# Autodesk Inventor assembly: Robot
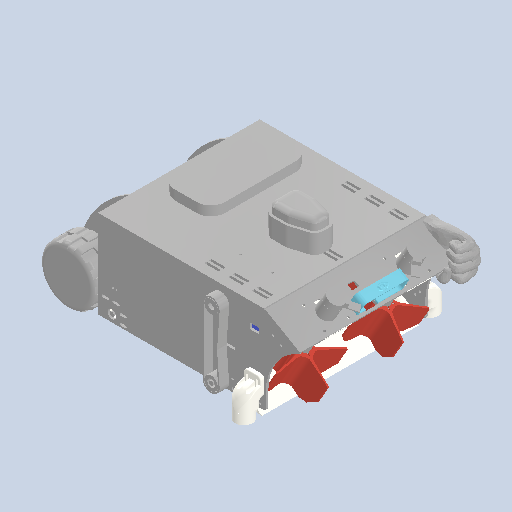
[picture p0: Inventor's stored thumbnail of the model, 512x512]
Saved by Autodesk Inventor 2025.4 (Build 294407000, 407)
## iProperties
Created: 2026-06
Part Number: Robot
Document SubType Name: Assembly
Designer: AdminForWorker
Title: Robot v95
Author: AdminForWorker
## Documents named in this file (14)
- c:\worker\convert-fusion-r03-cosv3\tmp\job-1\197\temp\files\732f0928-61d3-46c1-a194-566e71e2638b\9d352d10-8130-4545-9c63-16a8f3545512.iam
- c:\worker\convert-fusion-r03-cosv3\tmp\job-1\197\temp\files\732f0928-61d3-46c1-a194-566e71e2638b\Moteur + Roue v3.ipt
- c:\worker\convert-fusion-r03-cosv3\tmp\job-1\197\temp\files\732f0928-61d3-46c1-a194-566e71e2638b\Moteur v4.ipt
- c:\worker\convert-fusion-r03-cosv3\tmp\job-1\197\temp\files\732f0928-61d3-46c1-a194-566e71e2638b\Moteur v3(Symétrie miroir).ipt
- c:\worker\convert-fusion-r03-cosv3\tmp\job-1\197\temp\files\732f0928-61d3-46c1-a194-566e71e2638b\Moteur + Roue v1(Symétrie miroir).ipt
- c:\worker\convert-fusion-r03-cosv3\tmp\job-1\197\temp\files\732f0928-61d3-46c1-a194-566e71e2638b\Bille de manutention v16.ipt
- c:\worker\convert-fusion-r03-cosv3\tmp\job-1\197\temp\files\732f0928-61d3-46c1-a194-566e71e2638b\Bille + Main v7.ipt
- c:\worker\convert-fusion-r03-cosv3\tmp\job-1\197\temp\files\732f0928-61d3-46c1-a194-566e71e2638b\Camera v15.ipt
- c:\worker\convert-fusion-r03-cosv3\tmp\job-1\197\temp\files\732f0928-61d3-46c1-a194-566e71e2638b\OLD Frame.ipt
- c:\worker\convert-fusion-r03-cosv3\tmp\job-1\197\temp\files\732f0928-61d3-46c1-a194-566e71e2638b\Robot_Hélice v17.ipt
- c:\worker\convert-fusion-r03-cosv3\tmp\job-1\197\temp\files\732f0928-61d3-46c1-a194-566e71e2638b\Robot_Hélice v7(Symétrie miroir).ipt
- c:\worker\convert-fusion-r03-cosv3\tmp\job-1\197\temp\files\732f0928-61d3-46c1-a194-566e71e2638b\Frame.ipt
- c:\worker\convert-fusion-r03-cosv3\tmp\job-1\197\temp\files\732f0928-61d3-46c1-a194-566e71e2638b\Bille de manutention v16(Symétrie miroir).ipt
- c:\worker\convert-fusion-r03-cosv3\tmp\job-1\197\temp\files\732f0928-61d3-46c1-a194-566e71e2638b\Part26.ipt
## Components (14 placed, 13 different names)
1. Moteur + Roue v3:1
2. Moteur v4:2
3. Moteur v4:3
4. Moteur v3(Symétrie miroir):1
5. Moteur + Roue v1(Symétrie miroir):1
6. Bille de manutention v16:1
7. Bille + Main v7:1
8. Camera v15:1
9. OLD Frame:1
10. Robot_Hélice v17:1
11. Robot_Hélice v7(Symétrie miroir):1
12. Frame:1
13. Bille de manutention v16(Symétrie miroir):1
14. Part26
